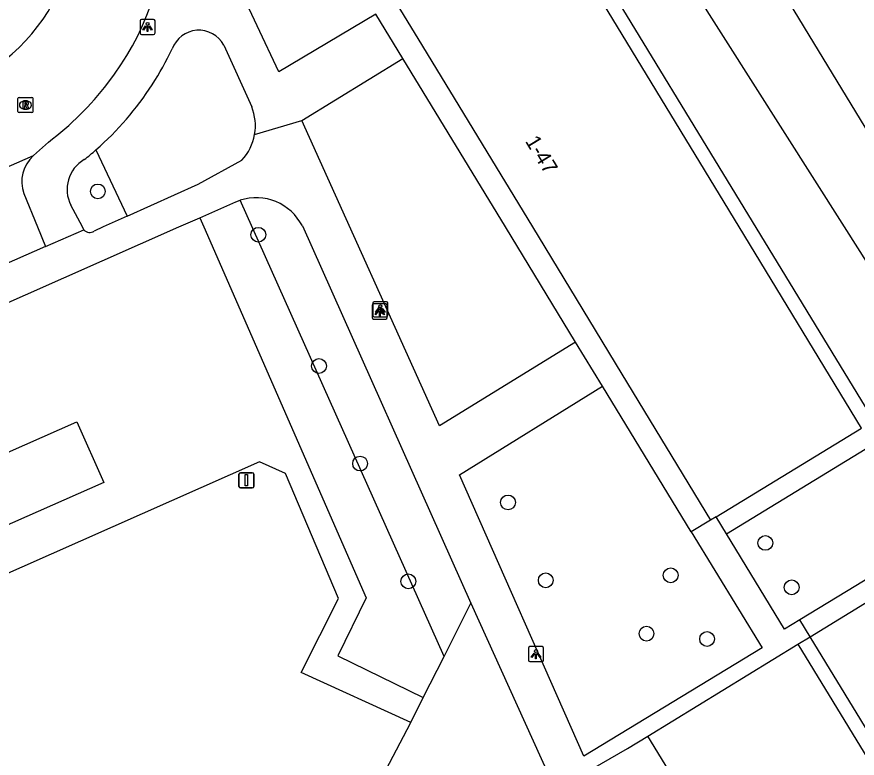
# Model space of a CAD drawing. Extents: x 159961 to 160856, y 382704 to 383353.
# Drawn here: x 160298.2 to 160353.9, y 382964.8 to 383013.9 of the extents above; entities that cross this region are included whole.
import ezdxf

# ---------------------------------------------------------------- set-up
doc = ezdxf.new("R2010")
doc.units = 0
for name, color, linetype in [('IMGEO_Boom', 7, 'Continuous'), ('IMGEO_Groenvoorziening', 7, 'Continuous'), ('IMGEO_Lichtpunt', 7, 'Continuous'), ('IMGEO_Pand', 7, 'Continuous'), ('IMGEO_Pand_nummerreeks', 7, 'Continuous'), ('IMGEO_Parkeervlak_open', 7, 'Continuous'), ('IMGEO_Rijbaan_lokaal_open', 7, 'Continuous'), ('IMGEO_Rioolput', 7, 'Continuous'), ('IMGEO_Verkeersbordpaal', 7, 'Continuous'), ('IMGEO_Voetpad_open', 7, 'Continuous')]:
    doc.layers.add(name, color=color, linetype=linetype)

msp = doc.modelspace()

# ---------------------------------------------------------------- linework, layer by layer
at = {"layer": 'IMGEO_Boom'}
for centre in [(160303.563, 383002.355), (160314.195, 382999.485), (160318.215, 382990.796), (160320.941, 382984.338), (160330.742, 382981.762), (160347.793, 382979.083), (160341.521, 382976.938), (160324.135, 382976.538), (160333.242, 382976.606), (160349.536, 382976.141), (160339.918, 382973.076), (160343.933, 382972.722)]:
    msp.add_circle(centre, 0.489, dxfattribs=at)
at = {"layer": 'IMGEO_Groenvoorziening'}
for points in [[(160335.219, 382992.368), (160330.567, 383000), (160323.762, 383011.165)], [(160303.438, 383005.107), (160305.494, 383000.706)], [(160326.499, 382971.558), (160312.984, 383001.767)], [(160342.867, 382979.821), (160336.996, 382989.452)]]:
    msp.add_lwpolyline(points, dxfattribs=at)
at = {"layer": 'IMGEO_Lichtpunt'}
for p, q in [((160306.356, 383013.652), (160306.356, 383012.845)), ((160306.356, 383013.652), (160306.356, 383012.845)), ((160307.258, 383013.747), (160306.45, 383013.747)), ((160307.258, 383013.747), (160306.45, 383013.747)), ((160307.352, 383012.845), (160307.352, 383013.652)), ((160307.352, 383012.845), (160307.352, 383013.652)), ((160306.45, 383012.751), (160307.258, 383012.751)), ((160306.45, 383012.751), (160307.258, 383012.751)), ((160321.742, 382994.808), (160321.742, 382994.001)), ((160321.742, 382994.808), (160321.742, 382994.001)), ((160321.782, 382994.958), (160321.782, 382994.151)), ((160321.782, 382994.958), (160321.782, 382994.151)), ((160322.644, 382994.903), (160321.836, 382994.903)), ((160322.644, 382994.903), (160321.836, 382994.903)), ((160322.684, 382995.053), (160321.876, 382995.053)), ((160322.684, 382995.053), (160321.876, 382995.053)), ((160322.738, 382994.001), (160322.738, 382994.808)), ((160322.738, 382994.001), (160322.738, 382994.808)), ((160322.778, 382994.151), (160322.778, 382994.958)), ((160322.778, 382994.151), (160322.778, 382994.958)), ((160321.836, 382993.907), (160322.644, 382993.907)), ((160321.836, 382993.907), (160322.644, 382993.907)), ((160321.876, 382994.057), (160322.684, 382994.057)), ((160321.876, 382994.057), (160322.684, 382994.057)), ((160332.093, 382972.124), (160332.093, 382971.317)), ((160332.093, 382972.124), (160332.093, 382971.317)), ((160332.995, 382972.219), (160332.187, 382972.219)), ((160332.995, 382972.219), (160332.187, 382972.219)), ((160333.089, 382971.317), (160333.089, 382972.124)), ((160333.089, 382971.317), (160333.089, 382972.124)), ((160332.187, 382971.223), (160332.995, 382971.223)), ((160332.187, 382971.223), (160332.995, 382971.223))]:
    msp.add_line(p, q, dxfattribs=at)
for points in [[(160306.73, 383013.316), (160306.769, 383013.288), (160306.581, 383013.026), (160306.543, 383013.053), (160306.73, 383013.316)], [(160306.832, 383013.268), (160306.879, 383013.268), (160306.879, 383012.946), (160306.832, 383012.946), (160306.832, 383013.268)], [(160306.942, 383013.288), (160306.98, 383013.315), (160307.167, 383013.053), (160307.128, 383013.025), (160306.942, 383013.288)], [(160322.116, 382994.472), (160322.155, 382994.444), (160321.967, 382994.182), (160321.929, 382994.209), (160322.116, 382994.472)], [(160322.156, 382994.622), (160322.195, 382994.594), (160322.007, 382994.332), (160321.969, 382994.359), (160322.156, 382994.622)], [(160322.218, 382994.424), (160322.265, 382994.424), (160322.265, 382994.102), (160322.218, 382994.102), (160322.218, 382994.424)], [(160322.258, 382994.574), (160322.305, 382994.574), (160322.305, 382994.252), (160322.258, 382994.252), (160322.258, 382994.574)], [(160322.328, 382994.444), (160322.366, 382994.471), (160322.553, 382994.209), (160322.514, 382994.181), (160322.328, 382994.444)], [(160322.368, 382994.594), (160322.406, 382994.621), (160322.593, 382994.359), (160322.554, 382994.331), (160322.368, 382994.594)], [(160332.467, 382971.788), (160332.506, 382971.76), (160332.318, 382971.498), (160332.28, 382971.525), (160332.467, 382971.788)], [(160332.569, 382971.74), (160332.616, 382971.74), (160332.616, 382971.418), (160332.569, 382971.418), (160332.569, 382971.74)], [(160332.679, 382971.76), (160332.717, 382971.787), (160332.904, 382971.525), (160332.865, 382971.497), (160332.679, 382971.76)]]:
    msp.add_lwpolyline(points, dxfattribs=at)
for centre in [(160306.855, 383013.45), (160322.241, 382994.606), (160322.281, 382994.756), (160332.592, 382971.922)]:
    msp.add_circle(centre, 0.0994, dxfattribs=at)
for centre, start, end in [((160306.45, 383013.652), 90, 180), ((160306.45, 383013.652), 90, 180), ((160307.258, 383013.652), 0, 90), ((160307.258, 383013.652), 0, 90), ((160306.45, 383012.845), 180, 270), ((160306.45, 383012.845), 180, 270), ((160307.258, 383012.845), 270, 0), ((160307.258, 383012.845), 270, 360), ((160321.836, 382994.808), 90, 180), ((160321.836, 382994.808), 90, 180), ((160321.876, 382994.958), 90, 180), ((160321.876, 382994.958), 90, 180), ((160322.644, 382994.808), 0, 90), ((160322.644, 382994.808), 0, 90), ((160322.684, 382994.958), 0, 90), ((160322.684, 382994.958), 0, 90), ((160321.876, 382994.151), 180, 270), ((160321.876, 382994.151), 180, 270), ((160322.684, 382994.151), 270, 0), ((160322.684, 382994.151), 270, 360), ((160321.836, 382994.001), 180, 270), ((160321.836, 382994.001), 180, 270), ((160322.644, 382994.001), 270, 0), ((160322.644, 382994.001), 270, 360), ((160332.187, 382972.124), 90, 180), ((160332.187, 382972.124), 90, 180), ((160332.995, 382972.124), 0, 90), ((160332.995, 382972.124), 0, 90), ((160332.187, 382971.317), 180, 270), ((160332.187, 382971.317), 180, 270), ((160332.995, 382971.317), 270, 0), ((160332.995, 382971.317), 270, 360)]:
    msp.add_arc(centre, 0.0946, start, end, dxfattribs=at)
at = {"layer": 'IMGEO_Pand'}
for points in [[(160354.153, 382986.675), (160346.052, 383000), (160327.335, 383030.788), (160317.351, 383024.674), (160323.309, 383014.872), (160325.073, 383011.971), (160332.352, 383000), (160336.511, 382993.16), (160338.283, 382990.248), (160344.157, 382980.593)], [(160344.524, 382980.816), (160354.153, 382986.675)], [(160344.524, 382980.816), (160344.157, 382980.593)], [(160340.008, 382966.298), (160349.953, 382972.37)], [(160349.953, 382972.37), (160376.799, 382928.407), (160366.855, 382922.334), (160360.992, 382931.935), (160359.171, 382934.918), (160347.7, 382953.702), (160345.878, 382956.686), (160340.008, 382966.298)]]:
    msp.add_lwpolyline(points, dxfattribs=at)
at = {"layer": 'IMGEO_Parkeervlak_open'}
msp.add_lwpolyline([(160330.218, 383037.075), (160336.761, 383035.598), (160350.986, 383012.188), (160358.396, 383000), (160363.112, 382992.243), (160362.536, 382990.002), (160358.735, 382991.005)], dxfattribs=at)
at = {"layer": 'IMGEO_Rijbaan_lokaal_open'}
for points in [[(160328.956, 383037.843), (160353.016, 383000), (160358.735, 382991.005)], [(160354.977, 382987.18), (160328.108, 383031.263), (160328.241, 383031.36), (160327.687, 383032.3)], [(160300.29, 383005.626), (160299.303, 383004.724)], [(160239.877, 382978.654), (160299.303, 383004.724)], [(160350.766, 382972.869), (160355.325, 382975.667), (160358.481, 382977.554)], [(160377.609, 382928.902), (160350.766, 382972.869)]]:
    msp.add_lwpolyline(points, dxfattribs=at)
for centre, radius, start, end in [((160289.815, 383020.776), 18.287, 321.9859, 359.2657), ((160289.455, 383021.029), 12.75, 291.9638, 336.4148), ((160287.842, 383022.152), 20.69, 306.9897, 322.351)]:
    msp.add_arc(centre, radius, start, end, dxfattribs=at)
at = {"layer": 'IMGEO_Rioolput'}
for p, q in [((160298.264, 383007.65), (160298.264, 383008.502)), ((160298.339, 383008.576), (160299.191, 383008.576)), ((160298.752, 383008.356), (160298.777, 383008.356)), ((160299.265, 383008.502), (160299.265, 383007.65)), ((160299.191, 383007.576), (160298.339, 383007.576)), ((160298.775, 383007.796), (160298.75, 383007.796))]:
    msp.add_line(p, q, dxfattribs=at)
for points in [[(160298.264, 383007.65), (160298.264, 383008.502)], [(160298.339, 383008.576), (160299.191, 383008.576)], [(160298.853, 383008.274), (160298.601, 383008.276), (160298.601, 383007.876)], [(160298.601, 383007.876), (160298.725, 383007.876), (160298.725, 383008.038), (160298.736, 383008.038)], [(160298.779, 383008.195), (160298.725, 383008.195), (160298.725, 383008.114)], [(160298.725, 383008.114), (160298.777, 383008.114)], [(160299.265, 383008.502), (160299.265, 383007.65)], [(160299.191, 383007.576), (160298.339, 383007.576)], [(160298.783, 383008.009), (160298.854, 383007.876), (160298.994, 383007.876), (160298.929, 383008.002)]]:
    msp.add_lwpolyline(points, dxfattribs=at)
for centre, radius, start, end in [((160298.341, 383008.5), 0.0765, 91.552, 178.448), ((160298.341, 383008.5), 0.0765, 91.552, 178.448), ((160298.735, 383007.985), 0.0533, 26.0293, 88.6989), ((160298.761, 383008.303), 0.19, 274.7715, 282.9687), ((160298.785, 383008.099), 0.0964, 77.0061, 93.1865), ((160298.799, 383008.156), 0.0378, 276.6634, 79.6772), ((160298.852, 383008.164), 0.109, 350.3612, 89.416), ((160298.85, 383008.164), 0.112, 277.5842, 350.9817), ((160298.834, 383007.949), 0.108, 29.5134, 73.7905), ((160299.189, 383008.5), 0.0765, 1.552, 88.448), ((160299.189, 383008.5), 0.0765, 1.552, 88.448), ((160298.341, 383007.652), 0.0765, 181.552, 268.448), ((160298.341, 383007.652), 0.0765, 181.552, 268.448), ((160299.189, 383007.652), 0.0765, 271.552, 358.448), ((160299.189, 383007.652), 0.0765, 271.552, 358.448)]:
    msp.add_arc(centre, radius, start, end, dxfattribs=at)
for centre, major_axis, ratio, start_param, end_param in [((160298.751, 383008.076), (-0.387, 0.002), 0.722429, 4.712389, 7.853982), ((160298.776, 383008.076), (-0.39, 0.002), 0.717154, 1.570796, 4.712389)]:
    msp.add_ellipse(centre, major_axis=major_axis, ratio=ratio, start_param=start_param, end_param=end_param, dxfattribs=at)
at = {"layer": 'IMGEO_Verkeersbordpaal'}
for p, q in [((160312.908, 382982.829), (160312.908, 382983.629)), ((160312.908, 382983.629), (160312.908, 382982.829)), ((160313.008, 382983.729), (160313.798, 382983.729)), ((160313.798, 382983.729), (160313.008, 382983.729)), ((160313.898, 382983.629), (160313.898, 382982.829)), ((160313.898, 382982.829), (160313.898, 382983.629)), ((160313.798, 382982.729), (160313.008, 382982.729)), ((160313.008, 382982.729), (160313.798, 382982.729))]:
    msp.add_line(p, q, dxfattribs=at)
msp.add_lwpolyline([(160313.328, 382983.604), (160313.478, 382983.604), (160313.478, 382982.854), (160313.328, 382982.854), (160313.328, 382983.604)], dxfattribs=at)
for centre, start, end in [((160313.008, 382983.629), 90, 180), ((160313.008, 382983.629), 90, 180), ((160313.798, 382983.629), 0, 90), ((160313.798, 382983.629), 360, 90), ((160313.008, 382982.829), 180, 270), ((160313.008, 382982.829), 180, 270), ((160313.798, 382982.829), 270, 0), ((160313.798, 382982.829), 270, 0)]:
    msp.add_arc(centre, 0.1, start, end, dxfattribs=at)
at = {"layer": 'IMGEO_Voetpad_open'}
for points in [[(160321.983, 383014.084), (160315.562, 383010.268), (160311.246, 383019.431)], [(160323.762, 383011.165), (160321.983, 383014.084)], [(160311.905, 383012.042), (160313.761, 383007.948)], [(160317.074, 383007.055), (160323.762, 383011.165)], [(160313.953, 383006.13), (160317.074, 383007.055)], [(160335.219, 382992.368), (160326.198, 382986.837), (160317.074, 383007.055)], [(160305.494, 383000.706), (160310.206, 383002.826), (160313.101, 383004.416)], [(160298.648, 383002.211), (160299.561, 383000), (160300.097, 382998.703)], [(160302.643, 382999.819), (160302.548, 383000), (160301.779, 383001.438)], [(160310.309, 383000.605), (160312.699, 383001.659), (160312.984, 383001.767)], [(160296.207, 382994.388), (160308.936, 383000), (160310.309, 383000.605)], [(160305.494, 383000.706), (160303.923, 383000), (160303.307, 382999.723)], [(160310.309, 383000.605), (160310.574, 383000), (160321.333, 382975.447), (160319.46, 382971.602), (160325.126, 382968.84)], [(160300.097, 382998.703), (160302.643, 382999.819)], [(160317.112, 383000.067), (160328.285, 382975.093)], [(160300.097, 382998.703), (160244.047, 382974.036), (160242.363, 382977.624)], [(160336.996, 382989.452), (160335.219, 382992.368)], [(160342.867, 382979.821), (160347.584, 382972.132), (160335.771, 382964.957), (160327.521, 382983.59), (160336.996, 382989.452)], [(160303.953, 382983.078), (160290.14, 382976.984), (160288.363, 382981.012), (160302.176, 382987.106), (160303.953, 382983.078)], [(160345.212, 382979.69), (160354.404, 382985.283), (160357.034, 382980.96), (160356.163, 382980.43), (160357.379, 382978.431), (160350.081, 382973.991)], [(160324.298, 382967.199), (160317.027, 382970.5), (160319.505, 382975.412), (160316.003, 382983.683), (160314.265, 382984.46), (160271.091, 382965.33), (160264.871, 382980.644)], [(160345.212, 382979.69), (160344.524, 382980.816)], [(160344.157, 382980.593), (160342.867, 382979.821)], [(160350.081, 382973.991), (160349.058, 382973.368), (160345.212, 382979.69)], [(160326.499, 382971.558), (160328.285, 382975.093)], [(160328.285, 382975.093), (160351.891, 382922.979)], [(160350.766, 382972.869), (160350.081, 382973.991)], [(160349.953, 382972.37), (160350.766, 382972.869)], [(160325.126, 382968.84), (160326.499, 382971.558)], [(160324.298, 382967.199), (160325.126, 382968.84)], [(160324.735, 382931.639), (160310.176, 382939.24), (160309.738, 382939.468), (160324.059, 382966.726), (160324.298, 382967.199)], [(160359.637, 382931.097), (160357.806, 382934.096), (160351.678, 382930.404), (160342.347, 382950.494), (160346.336, 382952.885), (160344.5, 382955.893), (160340.858, 382953.797), (160336.371, 382964.153), (160338.655, 382965.467), (160340.008, 382966.298)]]:
    msp.add_lwpolyline(points, dxfattribs=at)
for centre, radius, start, end in [((160310.253, 383011.149), 1.878, 28.3915, 159.9775), ((160289.807, 383020.663), 20.681, 327.0759, 334.5974), ((160289.744, 383020.703), 20.755, 311.2839, 327.0777), ((160310.666, 383006.702), 3.336, 350.1269, 21.9304), ((160310.65, 383006.703), 3.352, 316.9789, 350.1588), ((160300.872, 383002.973), 2.351, 131.8662, 198.9162), ((160289.496, 383020.999), 21.141, 308.5257, 311.26), ((160303.793, 383002.489), 2.272, 119.8101, 207.5443), ((160314.052, 382998.498), 3.439, 27.1459, 108.0883), ((160303.026, 383000.126), 0.491, 218.7045, 304.8421)]:
    msp.add_arc(centre, radius, start, end, dxfattribs=at)

# ---------------------------------------------------------------- texts
at = {"layer": 'IMGEO_Pand_nummerreeks'}
msp.add_text('1-47', height=1, rotation=301.3041, dxfattribs=at).set_placement((160331.851, 383005.68))

doc.saveas('drawing.dxf')
